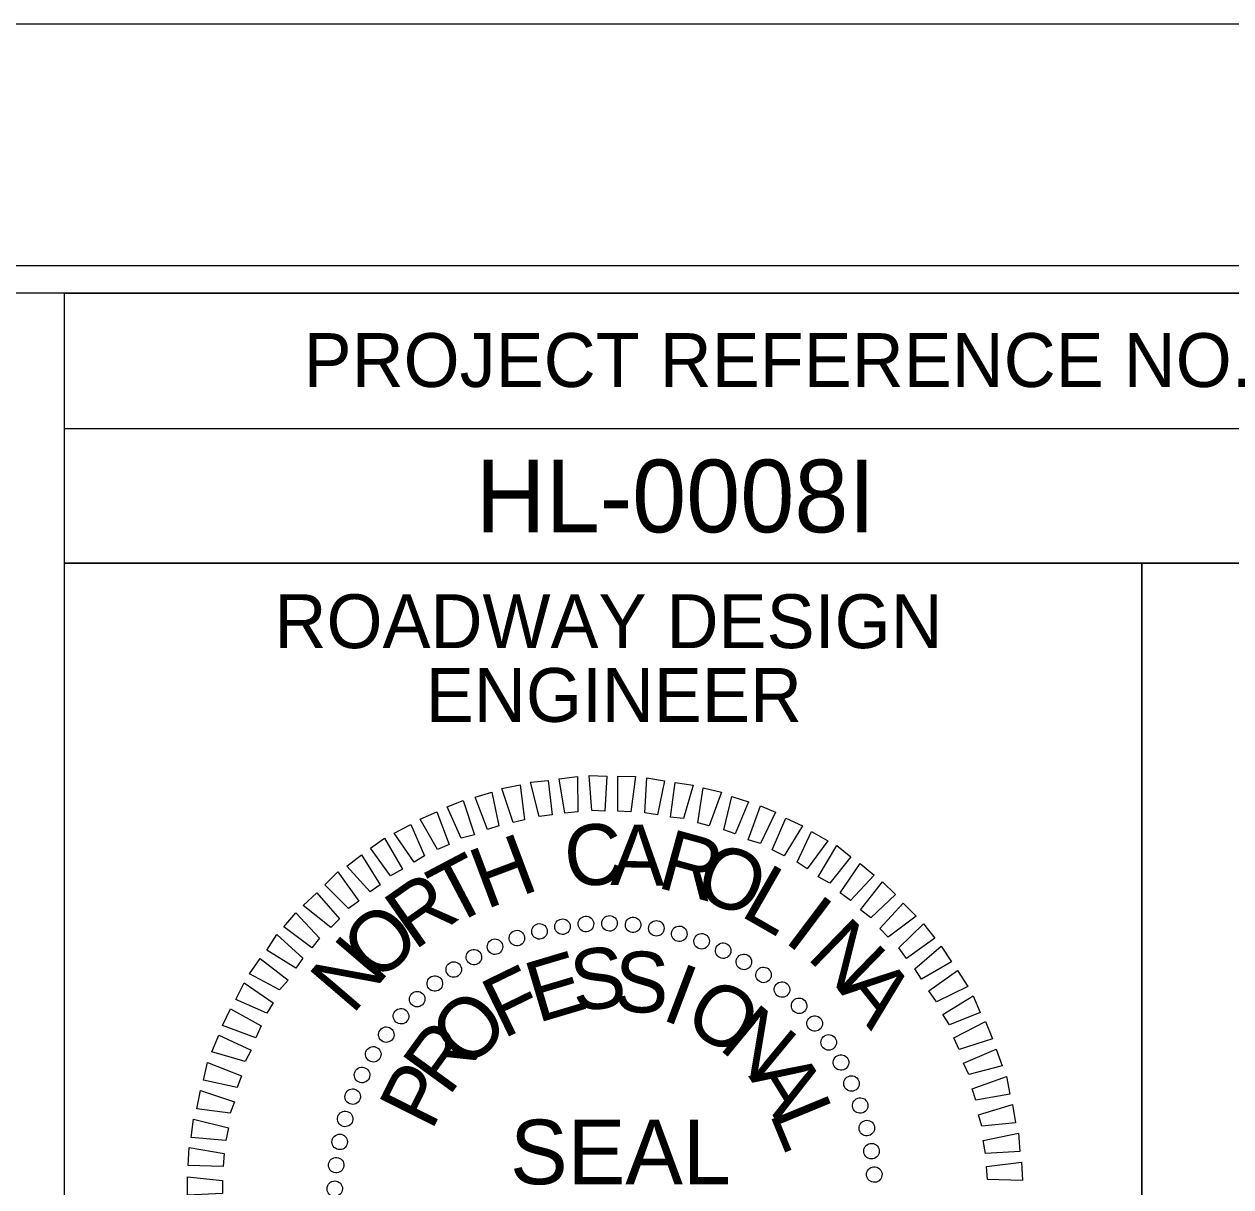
# Model space of a CAD drawing. Extents: x 3025871 to 3026431, y 707165 to 707825.
# Drawn here: x 3026241.5 to 3026258.31, y 707371.19 to 707387.38 of the extents above; entities that cross this region are included whole.
import ezdxf

# ---------------------------------------------------------------- set-up
doc = ezdxf.new("R2010")
doc.units = 0
for name, color, linetype in [('Old_Level_39', 7, 'Continuous'), ('Sheet Block Title CELL', 7, 'Continuous'), ('Sheet Cutting Line CELL', 7, 'Continuous'), ('Sheet Sticker Exception Certification CELL', 7, 'Continuous'), ('Typical Terminator CELL', 7, 'Continuous')]:
    doc.layers.add(name, color=color, linetype=linetype)

msp = doc.modelspace()

# ---------------------------------------------------------------- linework, layer by layer
at = {"layer": 'Old_Level_39'}
msp.add_lwpolyline([(3026273.948, 707384.017), (3026023.973, 707384.017), (3026023.973, 707225.752), (3026273.948, 707225.752)], close=True, dxfattribs=at)
at = {"layer": 'Sheet Block Title CELL'}
for p, q in [((3026249.328, 707374.854), (3026249.328, 707374.854)), ((3026249.658, 707374.862), (3026249.658, 707374.862)), ((3026249.988, 707374.839), (3026249.988, 707374.839)), ((3026248.676, 707374.749), (3026248.676, 707374.749)), ((3026249.006, 707374.809), (3026249.006, 707374.809)), ((3026250.311, 707374.787), (3026250.311, 707374.787)), ((3026250.626, 707374.719), (3026250.626, 707374.719)), ((3026248.061, 707374.539), (3026248.061, 707374.539)), ((3026248.361, 707374.659), (3026248.361, 707374.659)), ((3026250.941, 707374.614), (3026250.941, 707374.614)), ((3026247.768, 707374.389), (3026247.768, 707374.389)), ((3026251.241, 707374.479), (3026251.241, 707374.479)), ((3026251.533, 707374.329), (3026251.533, 707374.329)), ((3026247.483, 707374.217), (3026247.483, 707374.217)), ((3026247.221, 707374.029), (3026247.221, 707374.029)), ((3026251.803, 707374.142), (3026251.803, 707374.142)), ((3026252.066, 707373.939), (3026252.066, 707373.939)), ((3026246.973, 707373.804), (3026246.973, 707373.804)), ((3026252.298, 707373.714), (3026252.298, 707373.714)), ((3026246.748, 707373.572), (3026246.748, 707373.572)), ((3026252.523, 707373.467), (3026252.523, 707373.467)), ((3026246.546, 707373.309), (3026246.546, 707373.309)), ((3026252.711, 707373.204), (3026252.711, 707373.204)), ((3026246.358, 707373.039), (3026246.358, 707373.039)), ((3026252.883, 707372.919), (3026252.883, 707372.919)), ((3026246.208, 707372.747), (3026246.208, 707372.747)), ((3026253.033, 707372.627), (3026253.033, 707372.627)), ((3026246.073, 707372.447), (3026246.073, 707372.447)), ((3026253.153, 707372.327), (3026253.153, 707372.327)), ((3026245.968, 707372.132), (3026245.968, 707372.132)), ((3026253.243, 707372.012), (3026253.243, 707372.012)), ((3026245.901, 707371.817), (3026245.901, 707371.817)), ((3026253.303, 707371.682), (3026253.303, 707371.682)), ((3026245.848, 707371.494), (3026245.848, 707371.494)), ((3026253.348, 707371.359), (3026253.348, 707371.359))]:
    msp.add_line(p, q, dxfattribs=at)
for points in [[(3026248.676, 707376.347), (3026248.556, 707376.827), (3026248.803, 707376.849), (3026248.856, 707376.369)], [(3026249.036, 707376.392), (3026248.953, 707376.872), (3026249.208, 707376.902), (3026249.216, 707376.414)], [(3026249.411, 707376.429), (3026249.373, 707376.917), (3026249.621, 707376.909), (3026249.591, 707376.422)], [(3026249.771, 707376.422), (3026249.771, 707376.909), (3026250.018, 707376.902), (3026249.951, 707376.414)], [(3026250.146, 707376.399), (3026250.176, 707376.887), (3026250.423, 707376.842), (3026250.326, 707376.369)], [(3026247.956, 707376.167), (3026247.783, 707376.617), (3026248.016, 707376.684), (3026248.113, 707376.219)], [(3026248.316, 707376.264), (3026248.158, 707376.737), (3026248.413, 707376.789), (3026248.473, 707376.302)], [(3026250.506, 707376.339), (3026250.573, 707376.819), (3026250.821, 707376.782), (3026250.686, 707376.317)], [(3026250.888, 707376.257), (3026250.963, 707376.744), (3026251.218, 707376.684), (3026251.046, 707376.219)], [(3026247.588, 707376.047), (3026247.393, 707376.482), (3026247.618, 707376.572), (3026247.776, 707376.092)], [(3026251.248, 707376.159), (3026251.361, 707376.624), (3026251.593, 707376.549), (3026251.406, 707376.107)], [(3026247.258, 707375.889), (3026247.018, 707376.309), (3026247.251, 707376.414), (3026247.423, 707375.957)], [(3026251.586, 707376.024), (3026251.758, 707376.497), (3026251.968, 707376.407), (3026251.758, 707375.972)], [(3026246.936, 707375.709), (3026246.658, 707376.114), (3026246.891, 707376.234), (3026247.078, 707375.799)], [(3026251.923, 707375.882), (3026252.111, 707376.324), (3026252.343, 707376.219), (3026252.088, 707375.799)], [(3026246.606, 707375.522), (3026246.328, 707375.904), (3026246.523, 707376.047), (3026246.771, 707375.612)], [(3026252.268, 707375.709), (3026252.471, 707376.137), (3026252.696, 707376.009), (3026252.411, 707375.619)], [(3026252.561, 707375.507), (3026252.823, 707375.942), (3026253.018, 707375.784), (3026252.726, 707375.417)], [(3026246.321, 707375.297), (3026245.998, 707375.657), (3026246.201, 707375.814), (3026246.463, 707375.394)], [(3026252.868, 707375.282), (3026253.146, 707375.694), (3026253.341, 707375.529), (3026253.011, 707375.177)], [(3026246.021, 707375.064), (3026245.691, 707375.394), (3026245.871, 707375.574), (3026246.163, 707375.169)], [(3026253.153, 707375.049), (3026253.461, 707375.439), (3026253.641, 707375.259), (3026253.296, 707374.937)], [(3026245.773, 707374.802), (3026245.391, 707375.109), (3026245.578, 707375.282), (3026245.893, 707374.922)], [(3026245.511, 707374.517), (3026245.121, 707374.809), (3026245.286, 707375.004), (3026245.616, 707374.652)], [(3026253.423, 707374.787), (3026253.746, 707375.139), (3026253.926, 707374.959), (3026253.536, 707374.667)], [(3026253.686, 707374.517), (3026254.031, 707374.854), (3026254.188, 707374.652), (3026253.791, 707374.367)], [(3026245.286, 707374.232), (3026244.881, 707374.487), (3026245.023, 707374.704), (3026245.383, 707374.374)], [(3026253.911, 707374.224), (3026254.278, 707374.539), (3026254.421, 707374.322), (3026254.001, 707374.082)], [(3026245.061, 707373.932), (3026244.641, 707374.157), (3026244.791, 707374.367), (3026245.181, 707374.067)], [(3026254.106, 707373.917), (3026254.503, 707374.202), (3026254.646, 707373.977), (3026254.211, 707373.767)], [(3026244.881, 707373.609), (3026244.453, 707373.797), (3026244.566, 707374.029), (3026244.971, 707373.752)], [(3026254.301, 707373.587), (3026254.721, 707373.849), (3026254.818, 707373.617), (3026254.391, 707373.444)], [(3026244.731, 707373.264), (3026244.266, 707373.437), (3026244.378, 707373.669), (3026244.806, 707373.429)], [(3026254.451, 707373.264), (3026254.893, 707373.489), (3026254.991, 707373.249), (3026254.526, 707373.099)], [(3026244.581, 707372.934), (3026244.116, 707373.069), (3026244.213, 707373.302), (3026244.663, 707373.092)], [(3026254.586, 707372.912), (3026255.043, 707373.107), (3026255.126, 707372.874), (3026254.661, 707372.754)], [(3026244.468, 707372.574), (3026244.003, 707372.672), (3026244.056, 707372.919), (3026244.528, 707372.732)], [(3026254.706, 707372.552), (3026255.186, 707372.724), (3026255.231, 707372.477), (3026254.758, 707372.394)], [(3026244.371, 707372.214), (3026243.906, 707372.274), (3026243.958, 707372.529), (3026244.431, 707372.372)], [(3026254.796, 707372.192), (3026255.268, 707372.334), (3026255.313, 707372.079), (3026254.841, 707372.034)], [(3026244.311, 707371.832), (3026243.831, 707371.877), (3026243.861, 707372.132), (3026244.348, 707372.012)], [(3026254.863, 707371.832), (3026255.351, 707371.937), (3026255.373, 707371.682), (3026254.893, 707371.652)], [(3026244.273, 707371.472), (3026243.786, 707371.487), (3026243.801, 707371.734), (3026244.288, 707371.652)], [(3026254.908, 707371.472), (3026255.396, 707371.532), (3026255.411, 707371.277), (3026254.923, 707371.292)], [(3026244.266, 707371.097), (3026243.778, 707371.074), (3026243.778, 707371.329), (3026244.266, 707371.277)]]:
    msp.add_lwpolyline(points, close=True, dxfattribs=at)
for centre, major_axis in [((3026248.681, 707374.747), (-0.026, 0.105)), ((3026249.002, 707374.812), (-0.017, 0.107)), ((3026249.328, 707374.849), (-0.008, 0.108)), ((3026249.656, 707374.858), (0.002, 0.108)), ((3026249.984, 707374.838), (0.011, 0.107)), ((3026250.309, 707374.789), (0.021, 0.106)), ((3026250.628, 707374.713), (0.03, 0.104)), ((3026248.366, 707374.654), (-0.035, 0.102)), ((3026250.939, 707374.609), (0.039, 0.101)), ((3026247.767, 707374.387), (-0.0524, 0.0945)), ((3026248.061, 707374.533), (-0.0439, 0.0987)), ((3026251.24, 707374.478), (0.0473, 0.0971)), ((3026247.487, 707374.215), (-0.0604, 0.0895)), ((3026251.528, 707374.321), (0.0556, 0.0926)), ((3026251.802, 707374.14), (0.0635, 0.0874)), ((3026247.223, 707374.02), (-0.068, 0.0839)), ((3026252.059, 707373.936), (0.0709, 0.0815)), ((3026246.977, 707373.803), (-0.075, 0.0777)), ((3026252.297, 707373.71), (0.0777, 0.075)), ((3026246.752, 707373.565), (-0.0815, 0.0709)), ((3026252.514, 707373.464), (0.0839, 0.068)), ((3026246.547, 707373.308), (-0.0874, 0.0635)), ((3026252.71, 707373.2), (0.0895, 0.0604)), ((3026246.366, 707373.034), (-0.0926, 0.0556)), ((3026252.881, 707372.92), (0.0945, 0.0524)), ((3026246.209, 707372.746), (-0.0971, 0.0473)), ((3026253.027, 707372.627), (0.0987, 0.0439)), ((3026246.079, 707372.445), (-0.101, 0.039)), ((3026253.148, 707372.321), (0.102, 0.035)), ((3026245.974, 707372.134), (-0.104, 0.03)), ((3026253.241, 707372.007), (0.105, 0.026)), ((3026245.898, 707371.814), (-0.106, 0.021)), ((3026253.306, 707371.685), (0.107, 0.017)), ((3026245.849, 707371.49), (-0.107, 0.011)), ((3026253.344, 707371.359), (0.108, 0.008)), ((3026245.829, 707371.162), (-0.108, 0.002))]:
    msp.add_ellipse(centre, major_axis=major_axis, ratio=0.999708, dxfattribs=at)
at = {"layer": 'Sheet Cutting Line CELL'}
for p, q in [((3026242.065, 707381.752), (3026272.073, 707381.752)), ((3026257.073, 707379.877), (3026257.073, 707363.01))]:
    msp.add_line(p, q, dxfattribs=at)
for points in [[(3026272.073, 707383.635), (3026047.073, 707383.635), (3026047.073, 707226.135), (3026272.073, 707226.135)], [(3026242.065, 707383.635), (3026272.073, 707383.635), (3026272.073, 707379.877), (3026242.065, 707379.877)], [(3026242.065, 707379.877), (3026257.073, 707379.877), (3026257.073, 707363.002), (3026242.065, 707363.002)], [(3026257.073, 707379.877), (3026272.073, 707379.877), (3026272.073, 707363.002), (3026257.073, 707363.002)]]:
    msp.add_lwpolyline(points, close=True, dxfattribs=at)
at = {"layer": 'Typical Terminator CELL'}
msp.add_lwpolyline([(3026274.623, 707387.385), (3026022.023, 707387.385), (3026022.023, 707222.385), (3026274.623, 707222.385)], close=True, dxfattribs=at)

# ---------------------------------------------------------------- texts
at = {"layer": 'Sheet Block Title CELL'}
for s, height, rotation, p in [('C', 0.846, 6.2199, (3026249.073, 707375.349)), ('A', 0.846, 359.0203, (3026249.666, 707375.394)), ('H', 0.846, 20.6195, (3026247.933, 707375.049)), ('R', 0.846, 344.6211, (3026250.296, 707375.364)), ('T', 0.846, 27.8198, (3026247.446, 707374.802)), ('O', 0.846, 337.4212, (3026250.798, 707375.252)), ('R', 0.846, 35.0205, (3026246.936, 707374.472)), ('L', 0.846, 330.2209, (3026251.458, 707374.974)), ('I', 0.846, 323.0201, (3026252.066, 707374.614)), ('O', 0.846, 42.2217, (3026246.418, 707374.007)), ('N', 0.846, 315.8189, (3026252.388, 707374.382)), ('N', 0.846, 49.4235, (3026246.073, 707373.572)), ('S', 0.846, 7.2556, (3026249.171, 707373.624)), ('E', 0.846, 16.6111, (3026248.653, 707373.467)), ('S', 0.846, 357.9004, (3026249.711, 707373.632)), ('F', 0.846, 25.967, (3026248.173, 707373.242)), ('I', 0.846, 339.1896, (3026250.356, 707373.527)), ('A', 0.846, 308.6172, (3026252.831, 707373.939)), ('O', 0.846, 329.8335, (3026250.656, 707373.422)), ('O', 0.846, 44.6812, (3026247.678, 707372.799)), ('N', 0.846, 320.4766, (3026251.158, 707373.122)), ('R', 0.846, 54.0397, (3026247.416, 707372.432)), ('P', 0.846, 63.3989, (3026247.176, 707371.952)), ('A', 0.846, 301.7603, (3026251.586, 707372.732)), ('L', 0.846, 292.4008, (3026251.878, 707372.214)), ('SEAL', 0.8997, 360, (3026248.271, 707371.224))]:
    msp.add_text(s, height=height, rotation=rotation, dxfattribs=at).set_placement(p)
at = {"layer": 'Sheet Cutting Line CELL'}
for s, height, p in [('PROJECT REFERENCE NO.', 0.75001, (3026245.395, 707382.33)), ('ROADWAY DESIGN', 0.75001, (3026244.99, 707378.692)), ('ENGINEER', 0.75, (3026247.098, 707377.665))]:
    msp.add_text(s, height=height, rotation=360, dxfattribs=at).set_placement(p)
at = {"layer": 'Sheet Sticker Exception Certification CELL'}
msp.add_text('HL-0008I', height=1.0125, rotation=360, dxfattribs=at).set_placement((3026247.79, 707380.305))

doc.saveas('drawing.dxf')
